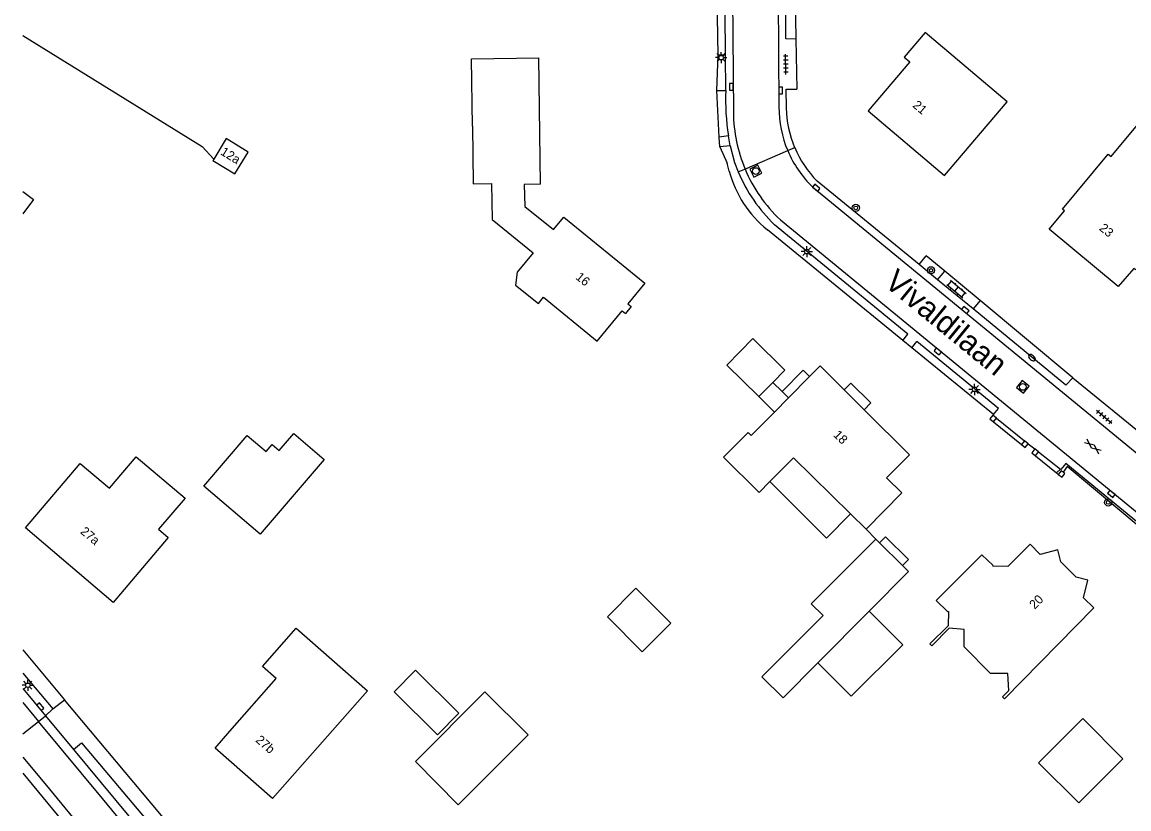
# Model space of a CAD drawing. Extents: x 137999 to 141000, y 397500 to 400501.
# Drawn here: x 137999.9 to 138123, y 398834.1 to 398921.5 of the extents above; entities that cross this region are included whole.
import ezdxf

# ---------------------------------------------------------------- set-up
doc = ezdxf.new("R2010")
doc.units = 0
for name, color, linetype in [('gg-afsc-erfafscheiding', 7, 'Continuous'), ('gg-afsc-hekwerk', 7, 'Continuous'), ('gg-afsc-muur', 7, 'Continuous'), ('gg-anno-huisnummerreeks BGT', 7, 'Continuous'), ('gg-anno-openbare ruimte label', 7, 'Continuous'), ('gg-bbg-bijgebouw', 7, 'Continuous'), ('gg-bbg-gedigitaliseerde bebouwing', 7, 'Continuous'), ('gg-bbg-gedigitaliseerde bijgebouw', 7, 'Continuous'), ('gg-bbg-hoofdgebouw', 7, 'Continuous'), ('gg-bbg-luifel en loopbrug', 7, 'Continuous'), ('gg-bbg-tussenscheiding', 7, 'Continuous'), ('gg-knt-verharding', 7, 'Continuous'), ('gg-knt-verharding nz', 7, 'Continuous'), ('gt-grn-groengrens', 7, 'Continuous'), ('gt-grn-vlakafsluiter', 7, 'Continuous'), ('gt-grn-weggrens', 7, 'Continuous'), ('gt-symb-boom', 7, 'Continuous'), ('gt-symb-brandkraan', 7, 'Continuous'), ('gt-symb-gesloten verharding', 7, 'Continuous'), ('gt-symb-klinker verharding', 7, 'Continuous'), ('gt-symb-kolk', 7, 'Continuous'), ('gt-symb-lichtmast', 7, 'Continuous'), ('gt-symb-rioolschacht', 7, 'Continuous'), ('gt-symb-tegel verharding', 7, 'Continuous')]:
    doc.layers.add(name, color=color, linetype=linetype)

# ---------------------------------------------------------------- blocks, each defined once
blk = doc.blocks.new('gt0-KOLK')
at = {"layer": 'gt-symb-kolk'}
blk.add_lwpolyline([(0, 0), (0.37, 0), (0.37, 0.4), (-0.38, 0.4), (-0.38, 0), (0, 0)], dxfattribs=at)
blk = doc.blocks.new('gt0-TEG1')
at = {"layer": 'gt-symb-tegel verharding'}
for p, q in [((-1.13, 0), (1.12, 0)), ((-0.9, -0.25), (-0.9, 0.25)), ((-0.45, -0.25), (-0.45, 0.25)), ((0, -0.25), (0, 0.25)), ((0.45, -0.25), (0.45, 0.25)), ((0.9, -0.25), (0.9, 0.25))]:
    blk.add_line(p, q, dxfattribs=at)
blk = doc.blocks.new('gt0-LMAST')
at = {"layer": 'gt-symb-lichtmast'}
for p, q in [((-0.18, 0.17), (-0.45, 0.44)), ((0, 0.25), (0, 0.62)), ((0.17, 0.17), (0.44, 0.44)), ((-0.25, 0), (-0.63, 0)), ((-0.18, -0.18), (-0.45, -0.45)), ((0, -0.25), (0, -0.63)), ((0.44, -0.45), (0.17, -0.18)), ((0.25, 0), (0.62, 0))]:
    blk.add_line(p, q, dxfattribs=at)
blk.add_circle((0, 0), 0.25, dxfattribs=at)
blk = doc.blocks.new('gt0-GESVH1')
at = {"layer": 'gt-symb-gesloten verharding'}
for p, q in [((-0.99, -0.26), (0.01, 0.24)), ((0.01, -0.26), (-0.99, 0.24)), ((0.01, 0.24), (1.01, -0.26)), ((1.01, 0.24), (0.01, -0.26))]:
    blk.add_line(p, q, dxfattribs=at)
blk = doc.blocks.new('gt0-RS')
at = {"layer": 'gt-symb-rioolschacht'}
blk.add_lwpolyline([(-0.5, -0.5), (0.5, -0.5), (0.5, 0.5), (-0.5, 0.5)], close=True, dxfattribs=at)
blk.add_circle((0, 0), 0.375, dxfattribs=at)
blk = doc.blocks.new('gt0-KL1')
at = {"layer": 'gt-symb-klinker verharding'}
for p, q in [((-1.15, 0.3), (1.15, 0.3)), ((-1, -0.3), (-1, 0.3)), ((-0.5, 0.3), (-0.5, 0.45)), ((0, -0.3), (0, 0.3)), ((0.5, 0.3), (0.5, 0.45)), ((1, -0.3), (1, 0.3)), ((-1.15, -0.3), (1.15, -0.3)), ((-0.5, -0.45), (-0.5, -0.3)), ((0.5, -0.45), (0.5, -0.3))]:
    blk.add_line(p, q, dxfattribs=at)
blk = doc.blocks.new('gt0-BR')
at = {"layer": 'gt-symb-brandkraan'}
for centre, radius, start, end in [((-0.24, 0), 0.206, 107.5669, 252.4331), ((0.6, -2.66), 3, 106.892, 107.5669), ((0, -0.69), 0.938, 73.108, 106.892), ((-0.6, -2.66), 3, 72.4331, 73.108), ((0.24, 0), 0.206, 287.567, 72.4331), ((0.6, 2.66), 3, 252.4331, 253.108), ((0, 0.69), 0.938, 253.108, 286.8921), ((-0.6, 2.66), 3, 286.8921, 287.567)]:
    blk.add_arc(centre, radius, start, end, dxfattribs=at)
blk = doc.blocks.new('gt0-BOOM')
at = {"layer": 'gt-symb-boom'}
for radius in [0.4, 0.2]:
    blk.add_circle((0, 0), radius, dxfattribs=at)

msp = doc.modelspace()

# ---------------------------------------------------------------- linework, layer by layer
at = {"layer": 'gg-afsc-erfafscheiding'}
for p, q in [((138085.64, 398949.86), (138085.94, 398919.64)), ((138077.31, 398917.87), (138076.97, 398941.9)), ((138077.16, 398913.95), (138077.31, 398917.87)), ((138078.53, 398904.98), (138078.32, 398905.85)), ((138097.84, 398886.15), (138082.79, 398898.44)), ((138102.52, 398893.85), (138100.46, 398895.57)), ((138106.45, 398890.58), (138102.52, 398893.85)), ((138116.75, 398881.99), (138106.45, 398890.58)), ((138098.85, 398885.33), (138097.84, 398886.15)), ((138107.92, 398877.92), (138098.85, 398885.33))]:
    msp.add_line(p, q, dxfattribs=at)
msp.add_lwpolyline([(138000, 398920.06), (138019.96, 398907.71), (138021.23, 398906.31)], dxfattribs=at)
msp.add_arc((138090.91, 398908.39), 12.84, 195.4023, 230.7637, dxfattribs=at)
at = {"layer": 'gg-afsc-hekwerk'}
for p, q in [((138077.44, 398908.76), (138077.16, 398913.95)), ((138077.5, 398907.69), (138077.44, 398908.76)), ((138107.94, 398877.11), (138111.03, 398874.58)), ((138112.61, 398873.33), (138114.92, 398871.43))]:
    msp.add_line(p, q, dxfattribs=at)
msp.add_lwpolyline([(138126.55, 398862.59), (138126.95, 398863.08), (138116.14, 398872.13), (138115.66, 398871.52)], dxfattribs=at)
at = {"layer": 'gg-afsc-muur'}
for p, q in [((138108.28, 398877.52), (138107.87, 398877.85)), ((138107.94, 398877.11), (138108.28, 398877.52)), ((138111.37, 398874.98), (138111.03, 398874.58)), ((138111.78, 398874.64), (138111.37, 398874.98)), ((138112.94, 398873.75), (138112.53, 398874.08)), ((138112.61, 398873.33), (138112.94, 398873.75)), ((138093.76, 398865.15), (138094.84, 398864.07))]:
    msp.add_line(p, q, dxfattribs=at)
for points in [[(138107.87, 398877.85), (138107.53, 398877.44), (138107.94, 398877.11)], [(138111.03, 398874.58), (138111.44, 398874.24), (138111.78, 398874.64)], [(138112.53, 398874.08), (138112.2, 398873.66), (138112.61, 398873.33)], [(138115.66, 398871.52), (138115.47, 398871.67), (138115.13, 398871.25)], [(138115.13, 398871.25), (138115.55, 398870.93), (138115.88, 398871.34), (138115.66, 398871.52)]]:
    msp.add_lwpolyline(points, dxfattribs=at)
at = {"layer": 'gg-bbg-bijgebouw'}
for p, q in [((138094.84, 398864.07), (138095.27, 398863.65)), ((138095.27, 398863.65), (138097.8, 398861.12)), ((138097.8, 398861.12), (138098.47, 398860.45))]:
    msp.add_line(p, q, dxfattribs=at)
at = {"layer": 'gg-bbg-gedigitaliseerde bebouwing'}
msp.add_line((138093.76, 398865.15), (138092.02, 398866.86), dxfattribs=at)
for points in [[(138050, 398909.97), (138049.9, 398917.47), (138057.39, 398917.57)], [(138115.62, 398900.75), (138120.68, 398906.85), (138121, 398906.59), (138125.97, 398912.58), (138126.59, 398912.06)], [(138050, 398909.97), (138050.09, 398903.56), (138052.12, 398903.59), (138052.18, 398899.6), (138056.73, 398895.9), (138054.97, 398893.75), (138054.79, 398892.31), (138057.33, 398890.25), (138057.9, 398890.95), (138063.88, 398886.08), (138066.65, 398889.45), (138067, 398889.16)], [(138000.29, 398865.31), (138006.38, 398872.47), (138009.63, 398869.71), (138012.61, 398873.22), (138018.04, 398868.61), (138015.1, 398865.15), (138016.17, 398864.24), (138010.03, 398857.03)], [(138083.07, 398870.45), (138081.86, 398869.24), (138077.91, 398873.17)], [(138092.02, 398866.86), (138085.7, 398873.1), (138083.07, 398870.45)], [(138119.07, 398856.4), (138109.15, 398846.31), (138108.95, 398846.51), (138109.65, 398847.22), (138109.53, 398849.12), (138107.61, 398849.11), (138104.67, 398852.09), (138104.66, 398854.02), (138103.01, 398854.14), (138101.06, 398852.2), (138100.86, 398852.4), (138102.9, 398854.43)], [(138023.03, 398842.7), (138028.17, 398848.56), (138026.66, 398849.88), (138030.41, 398854.16)], [(138030.41, 398854.16), (138038.33, 398847.19), (138027.76, 398835.22)]]:
    msp.add_lwpolyline(points, dxfattribs=at)
at = {"layer": 'gg-bbg-gedigitaliseerde bijgebouw'}
for p, q in [((138081.83, 398879.9), (138083.4, 398881.49)), ((138084.42, 398880.48), (138085.14, 398879.77)), ((138087.67, 398856.88), (138094.84, 398864.07)), ((138098.47, 398860.45), (138094.09, 398856.05))]:
    msp.add_line(p, q, dxfattribs=at)
for points in [[(138083.4, 398881.49), (138084.73, 398882.84), (138081.18, 398886.35), (138078.28, 398883.41), (138081.83, 398879.9)], [(138087.47, 398882.14), (138086.76, 398882.85), (138084.42, 398880.48)], [(138020.14, 398869.94), (138024.96, 398875.58), (138027.05, 398873.8), (138027.72, 398874.59), (138028.51, 398873.91), (138030.14, 398875.82), (138033.51, 398872.93), (138026.39, 398864.6), (138020.14, 398869.94)], [(138087.67, 398856.88), (138088.98, 398855.57), (138082.19, 398848.76), (138084.53, 398846.42), (138088.39, 398850.29)], [(138094.09, 398856.05), (138097.84, 398852.31), (138092.12, 398846.58), (138088.39, 398850.29)], [(138043.67, 398849.49), (138048.49, 398844.69), (138046.11, 398842.29), (138041.28, 398847.08), (138043.67, 398849.49)], [(138043.68, 398839.35), (138048.42, 398834.5), (138056.2, 398842.3), (138051.39, 398847.09), (138043.68, 398839.35)], [(138112.95, 398839.19), (138117.43, 398834.72), (138122.33, 398839.64), (138117.85, 398844.11), (138112.95, 398839.19)]]:
    msp.add_lwpolyline(points, dxfattribs=at)
at = {"layer": 'gg-bbg-hoofdgebouw'}
for p, q in [((138057.58, 398903.52), (138057.39, 398917.57)), ((138102.5, 398904.5), (138109.44, 398912.7)), ((138093.56, 398878.44), (138091.33, 398880.66)), ((138085.14, 398879.77), (138083.57, 398878.18)), ((138098.58, 398873.44), (138093.56, 398878.44)), ((138010.03, 398857.03), (138000.29, 398865.31))]:
    msp.add_line(p, q, dxfattribs=at)
for points in [[(138109.44, 398912.7), (138100.33, 398920.41), (138098.01, 398917.65), (138098.62, 398917.13), (138094.01, 398911.7), (138102.5, 398904.5)], [(138021.23, 398906.31), (138021.14, 398906.16), (138023.57, 398904.66), (138025.07, 398907.09), (138022.63, 398908.59), (138021.23, 398906.31)], [(138057.58, 398903.52), (138055.76, 398903.49), (138055.82, 398901.06), (138059.02, 398898.47), (138060.14, 398899.87), (138069.16, 398892.53), (138067.28, 398890.22), (138067.63, 398889.94), (138067, 398889.16)], [(138123.75, 398894.01), (138123.54, 398894.15), (138121.81, 398892.14), (138114.12, 398898.51), (138115.83, 398900.57), (138115.62, 398900.75)], [(138091.33, 398880.66), (138088.65, 398883.33), (138087.47, 398882.14)], [(138083.57, 398878.18), (138081, 398875.58), (138080.65, 398875.93), (138077.91, 398873.17)], [(138098.58, 398873.44), (138096.05, 398870.88), (138097.74, 398869.19), (138093.76, 398865.15)], [(138112, 398863.48), (138109.54, 398861.01), (138107.87, 398861.04), (138107.88, 398861.12), (138106.63, 398862.33), (138101.54, 398857.23), (138102.8, 398856), (138102.91, 398856.01), (138102.9, 398854.43)], [(138119.07, 398856.4), (138117.93, 398857.52), (138118.43, 398859.48), (138117.13, 398859.84), (138115.41, 398861.54), (138115.08, 398862.85), (138113.11, 398862.36), (138112, 398863.48)], [(138027.76, 398835.22), (138021.39, 398840.83), (138023.03, 398842.7)]]:
    msp.add_lwpolyline(points, dxfattribs=at)
at = {"layer": 'gg-bbg-luifel en loopbrug'}
for p, q in [((138083.4, 398881.49), (138084.42, 398880.48)), ((138081.83, 398879.9), (138083.57, 398878.18))]:
    msp.add_line(p, q, dxfattribs=at)
for points in [[(138000, 398902.71), (138001.19, 398901.83), (138000, 398900.22)], [(138093.56, 398878.44), (138094.31, 398879.2), (138092.08, 398881.41), (138091.33, 398880.66)], [(138083.07, 398870.45), (138089.35, 398864.18), (138092.02, 398866.86)], [(138097.8, 398861.12), (138098.47, 398861.8), (138095.94, 398864.33), (138095.27, 398863.65)], [(138065, 398855.4), (138068.18, 398858.59), (138072.07, 398854.72), (138068.88, 398851.52), (138065, 398855.4)]]:
    msp.add_lwpolyline(points, dxfattribs=at)
at = {"layer": 'gg-bbg-tussenscheiding'}
for p, q in [((138087.47, 398882.14), (138085.14, 398879.77)), ((138094.09, 398856.05), (138088.39, 398850.29))]:
    msp.add_line(p, q, dxfattribs=at)
at = {"layer": 'gg-knt-verharding'}
for p, q in [((138078.71, 398950.23), (138079.01, 398911.48)), ((138083.81, 398949.79), (138084.07, 398912.12)), ((138085.94, 398919.64), (138086.06, 398914.1)), ((138078.16, 398913.93), (138078.14, 398917.89)), ((138077.16, 398913.95), (138078.16, 398913.93)), ((138078.66, 398907.8), (138077.5, 398907.69)), ((138099.65, 398894.58), (138088.32, 398903.87)), ((138087.84, 398903.18), (138138.44, 398861.65)), ((138098.42, 398886.85), (138083.59, 398899.02)), ((138084.23, 398899.55), (138169.85, 398829.32)), ((138101.71, 398892.89), (138099.65, 398894.58)), ((138101.71, 398892.89), (138102.52, 398893.85)), ((138105.67, 398889.65), (138101.71, 398892.89)), ((138106.45, 398890.58), (138105.67, 398889.65)), ((138097.84, 398886.15), (138098.42, 398886.85)), ((138098.85, 398885.33), (138099.42, 398886.03)), ((138108.48, 398878.6), (138099.42, 398886.03)), ((138116.75, 398881.99), (138124.94, 398875.31)), ((138107.87, 398877.85), (138107.92, 398877.92)), ((138107.92, 398877.92), (138108.48, 398878.6)), ((138111.78, 398874.64), (138112.53, 398874.08)), ((138115.38, 398871.84), (138114.92, 398871.43)), ((138000, 398851.75), (138004.64, 398846.2)), ((138000, 398849.16), (138003.34, 398845.17)), ((138000, 398847.45), (138002.53, 398844.4)), ((138003.34, 398845.17), (138002.53, 398844.4)), ((138002.53, 398844.4), (138005.63, 398840.68)), ((138005.63, 398840.68), (138019.95, 398823.44)), ((138000, 398838.04), (138007.52, 398828.94))]:
    msp.add_line(p, q, dxfattribs=at)
for points in [[(138085.94, 398919.64), (138084.85, 398919.67), (138084.64, 398949.8)], [(138078.14, 398917.89), (138077.96, 398941.87), (138076.97, 398941.9)], [(138084.9, 398911.98), (138084.89, 398914.1), (138086.06, 398914.1)], [(138078.66, 398907.8), (138079.15, 398905.95), (138079.55, 398904.89)], [(138116.75, 398881.99), (138115.98, 398881.19), (138105.67, 398889.65)], [(138127.34, 398863.11), (138115.97, 398872.46), (138115.42, 398871.8), (138115.38, 398871.84)], [(138050.73, 398799.63), (138025.05, 398821.82), (138004.64, 398846.2)], [(138005.63, 398840.68), (138006.54, 398841.41), (138020.92, 398824.34), (138019.95, 398823.44)]]:
    msp.add_lwpolyline(points, dxfattribs=at)
for centre, radius, start, end in [((138095.63, 398911.64), 16.62, 180.5717, 202.7684), ((138096.51, 398912.1), 12.44, 179.9103, 202.909), ((138096.72, 398912.19), 11.83, 181.0299, 202.8738), ((138096.73, 398912.19), 11.83, 202.8709, 224.7079), ((138096.51, 398912.1), 12.44, 202.9008, 225.7984), ((138095.62, 398911.64), 16.61, 202.7685, 226.7059), ((138095.77, 398911.72), 17.6, 202.8343, 226.1711)]:
    msp.add_arc(centre, radius, start, end, dxfattribs=at)
at = {"layer": 'gg-knt-verharding nz'}
for p, q in [((138078.46, 398908.91), (138077.44, 398908.76)), ((138078.66, 398907.8), (138078.46, 398908.91)), ((138108.28, 398877.52), (138111.37, 398874.98)), ((138112.94, 398873.75), (138115.38, 398871.84)), ((138000, 398845.89), (138001.74, 398843.79))]:
    msp.add_line(p, q, dxfattribs=at)
for points in [[(138075.31, 398771.05), (138049.75, 398793.28), (138039.2, 398802.38), (138036.17, 398805.03), (138033.13, 398807.74), (138030.29, 398810.47), (138027.41, 398813.43), (138024.7, 398816.36), (138021.94, 398819.45), (138019.29, 398822.56), (138008.86, 398835.21), (138001.74, 398843.79)], [(138000, 398839.8), (138002.63, 398836.65), (138016.94, 398819.26), (138019.68, 398816.09), (138022.38, 398813.1), (138025.16, 398810.16), (138028.05, 398807.18), (138031.03, 398804.24), (138034.11, 398801.46), (138037.19, 398798.78), (138048.01, 398789.44), (138060.56, 398778.57), (138072.43, 398767.99)]]:
    msp.add_lwpolyline(points, dxfattribs=at)
msp.add_arc((138103.95, 398912.91), 25.81, 177.7247, 188.9227, dxfattribs=at)
at = {"layer": 'gt-grn-groengrens'}
for p, q in [((138078.14, 398917.89), (138077.31, 398917.87)), ((138077.5, 398907.69), (138078.32, 398905.85)), ((138099.65, 398894.58), (138100.46, 398895.57))]:
    msp.add_line(p, q, dxfattribs=at)
at = {"layer": 'gt-grn-vlakafsluiter'}
msp.add_line((138115.13, 398871.25), (138114.92, 398871.43), dxfattribs=at)
at = {"layer": 'gt-grn-weggrens'}
for p, q in [((138085.05, 398907.26), (138085.83, 398907.59)), ((138080.3, 398905.21), (138085.05, 398907.26)), ((138079.55, 398904.89), (138080.3, 398905.21)), ((138003.34, 398845.17), (138004.64, 398846.2)), ((138000, 398842.42), (138001.74, 398843.79)), ((138001.74, 398843.79), (138002.53, 398844.4))]:
    msp.add_line(p, q, dxfattribs=at)

# ---------------------------------------------------------------- block references
at = {"layer": 'gt-symb-boom'}
for p in [(138092.62, 398900.89), (138100.98, 398893.95), (138120.69, 398868.14)]:
    msp.add_blockref('gt0-BOOM', p, dxfattribs=at)
at = {"layer": 'gt-symb-brandkraan', "rotation": 140.64204307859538}
msp.add_blockref('gt0-BR', (138112.2, 398884.24), dxfattribs=at)
at = {"layer": 'gt-symb-gesloten verharding', "rotation": -38.990994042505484}
msp.add_blockref('gt0-GESVH1', (138118.98, 398874.38), dxfattribs=at)
at = {"layer": 'gt-symb-klinker verharding', "rotation": -39.64417495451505}
msp.add_blockref('gt0-KL1', (138103.83, 398891.87), dxfattribs=at)
at = {"layer": 'gt-symb-kolk'}
for p, rotation in [((138078.99, 398914.36), 90.45835645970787), ((138084.46, 398913.94), 90.45835645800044), ((138088.1, 398902.96), -39.35795692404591), ((138104.67, 398889.38), -39.357956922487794), ((138101.61, 398884.77), -39.35795692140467), ((138120.91, 398868.93), -39.35795692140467), ((138001.79, 398845.29), -50.275137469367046)]:
    msp.add_blockref('gt0-KOLK', p, dxfattribs=dict(at, rotation=rotation))
at = {"layer": 'gt-symb-lichtmast'}
for p in [(138077.65, 398917.6), (138087.17, 398896.03), (138105.82, 398880.71), (138000.56, 398847.81)]:
    msp.add_blockref('gt0-LMAST', p, dxfattribs=at)
at = {"layer": 'gt-symb-rioolschacht'}
for p, rotation in [((138081.5, 398904.98), 25.97571465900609), ((138111.19, 398880.98), -39.357956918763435)]:
    msp.add_blockref('gt0-RS', p, dxfattribs=dict(at, rotation=rotation))
at = {"layer": 'gt-symb-tegel verharding'}
for p, rotation in [((138084.84, 398916.87), 90.97393443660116), ((138120.24, 398877.64), 139.98904227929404)]:
    msp.add_blockref('gt0-TEG1', p, dxfattribs=dict(at, rotation=rotation))

# ---------------------------------------------------------------- texts
at = {"layer": 'gg-anno-huisnummerreeks BGT'}
for s, rotation, p in [('21', 319.7, (138098.87, 398912.17)), ('12a', 328.5, (138021.9, 398906.88)), ('23', 320.4, (138119.61, 398898.5)), ('16', 320.9, (138061.39, 398893.05)), ('18', 315.1, (138090.06, 398875.58)), ('27a', 319.6, (138006.32, 398864.78)), ('20', 45, (138112.51, 398856.21)), ('27b', 318.6, (138025.81, 398841.6))]:
    msp.add_text(s, height=1, rotation=rotation, dxfattribs=at).set_placement(p)
at = {"layer": 'gg-anno-openbare ruimte label'}
msp.add_text('Vivaldilaan', height=2.5, rotation=320.7, dxfattribs=at).set_placement((138095.65, 398892.32))

doc.saveas('drawing.dxf')
